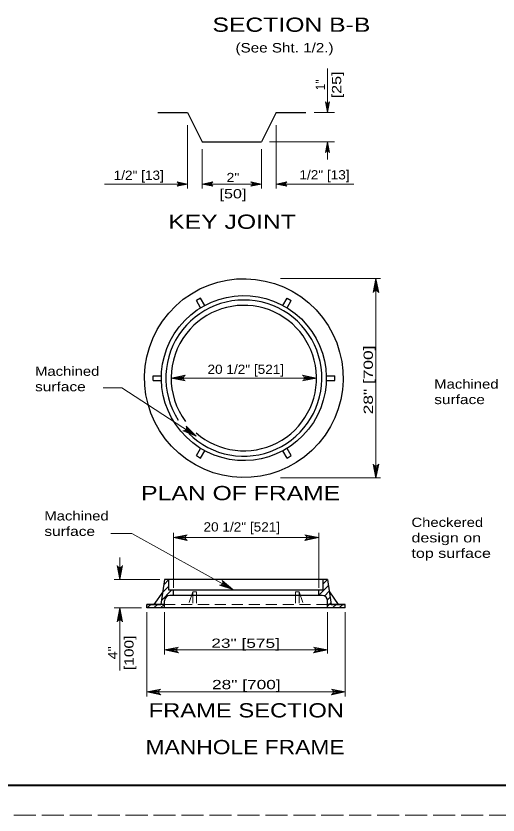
# Model space of a CAD drawing. Extents: x 758.3 to 792.3, y 849.7 to 893.7.
# Drawn here: x 775.35 to 783.49, y 849.69 to 863.16 of the extents above; entities that cross this region are included whole.
import ezdxf
from ezdxf.enums import TextEntityAlignment as Align

# ---------------------------------------------------------------- set-up
doc = ezdxf.new("R2010")
doc.units = 0
doc.header["$LTSCALE"] = 0.062
doc.linetypes.add('LONG_DASHED', pattern=[7.5, 6, -1.5])
doc.linetypes.add('MEDIUM_DASHED', pattern=[4.5, 3, -1.5])
doc.layers.add('1', color=7, linetype='Continuous', lineweight=13)

msp = doc.modelspace()

# ---------------------------------------------------------------- linework, layer by layer
at = {"layer": '1'}
for p, q in [((780.60933, 861.53942), (780.60933, 862.2805)), ((780.58692, 861.69967), (780.60933, 861.53942)), ((780.63408, 861.7015), (780.60933, 861.53942)), ((780.598, 861.69425), (780.60933, 861.53942)), ((780.62375, 861.69542), (780.60933, 861.53942)), ((780.60933, 861.69258), (780.60933, 861.53942)), ((780.38242, 861.53808), (780.72908, 861.53808)), ((778.24467, 861.32258), (778.24467, 860.253)), ((779.74392, 861.32258), (779.74392, 860.253)), ((779.63217, 861.03967), (780.72908, 861.03967)), ((780.58458, 860.87758), (780.60933, 861.03967)), ((780.59492, 860.88367), (780.60933, 861.03967)), ((780.60933, 860.74433), (780.60933, 861.03967)), ((780.60933, 860.8865), (780.60933, 861.03967)), ((780.62067, 860.88483), (780.60933, 861.03967)), ((780.63175, 860.87942), (780.60933, 861.03967)), ((778.4945, 860.91733), (778.4945, 860.253)), ((779.494, 860.91733), (779.494, 860.253)), ((778.08442, 860.35233), (778.24467, 860.32992)), ((778.65475, 860.35233), (778.4945, 860.32992)), ((779.33383, 860.35233), (779.494, 860.32992)), ((779.90417, 860.35233), (779.74392, 860.32992)), ((776.84475, 860.32992), (778.24467, 860.32992)), ((778.0825, 860.30508), (778.24467, 860.32992)), ((778.08867, 860.3155), (778.24467, 860.32992)), ((778.08983, 860.34125), (778.24467, 860.32992)), ((778.0915, 860.32992), (778.24467, 860.32992)), ((778.64933, 860.34125), (778.4945, 860.32992)), ((778.64767, 860.32992), (778.4945, 860.32992)), ((778.6505, 860.3155), (778.4945, 860.32992)), ((778.65667, 860.30508), (778.4945, 860.32992)), ((779.33192, 860.30508), (779.494, 860.32992)), ((779.33808, 860.3155), (779.494, 860.32992)), ((779.33925, 860.34125), (779.494, 860.32992)), ((779.34092, 860.32992), (779.494, 860.32992)), ((779.89875, 860.34125), (779.74392, 860.32992)), ((779.74392, 860.32992), (781.05142, 860.32992)), ((779.89708, 860.32992), (779.74392, 860.32992)), ((779.89992, 860.3155), (779.74392, 860.32992)), ((779.90608, 860.30508), (779.74392, 860.32992)), ((779.81358, 858.73542), (781.50583, 858.73542)), ((781.39425, 858.51958), (781.42717, 858.73542)), ((781.408, 858.52775), (781.42717, 858.73542)), ((781.42717, 858.53158), (781.42717, 858.73542)), ((781.44225, 858.52933), (781.42717, 858.73542)), ((781.457, 858.52217), (781.42717, 858.73542)), ((778.18233, 857.08708), (777.96908, 857.05725)), ((778.17517, 857.07233), (777.96908, 857.05725)), ((779.59, 857.05725), (777.96908, 857.05725)), ((778.17292, 857.05725), (777.96908, 857.05725)), ((778.17675, 857.03808), (777.96908, 857.05725)), ((778.18492, 857.02433), (777.96908, 857.05725)), ((779.59, 857.05725), (780.4235, 857.05725)), ((780.20767, 857.02433), (780.4235, 857.05725)), ((780.21017, 857.08708), (780.4235, 857.05725)), ((780.21583, 857.03808), (780.4235, 857.05725)), ((780.21742, 857.07233), (780.4235, 857.05725)), ((780.21958, 857.05725), (780.4235, 857.05725)), ((778.21125, 856.18008), (778.38992, 856.07633)), ((778.22158, 856.19133), (778.38992, 856.07633)), ((778.22925, 856.20925), (778.38992, 856.07633)), ((778.23033, 856.22525), (778.38992, 856.07633)), ((778.19692, 856.172), (778.38992, 856.07633)), ((781.39733, 855.58467), (781.42717, 855.37133)), ((781.41208, 855.57742), (781.42717, 855.37133)), ((781.46017, 855.58717), (781.42717, 855.37133)), ((781.44633, 855.579), (781.42717, 855.37133)), ((781.42717, 855.57525), (781.42717, 855.37133)), ((779.81358, 855.37775), (781.50583, 855.37775)), ((778.00583, 853.51958), (778.00583, 854.44617)), ((780.46033, 853.51958), (780.46033, 854.44617)), ((778.21908, 854.39733), (778.00583, 854.3675)), ((778.21183, 854.38258), (778.00583, 854.3675)), ((778.20967, 854.3675), (778.00583, 854.3675)), ((778.21342, 854.34833), (778.00583, 854.3675)), ((778.22158, 854.3345), (778.00583, 854.3675)), ((780.46033, 854.3675), (778.00583, 854.3675)), ((780.2445, 854.3345), (780.46033, 854.3675)), ((780.24708, 854.39733), (780.46033, 854.3675)), ((780.25275, 854.34833), (780.46033, 854.3675)), ((780.25425, 854.38258), (780.46033, 854.3675)), ((780.2565, 854.3675), (780.46033, 854.3675)), ((778.00583, 853.973), (778.00583, 854.26283)), ((780.46033, 853.973), (780.46033, 854.26283)), ((777.10258, 853.6595), (777.10258, 854.03017)), ((777.07275, 853.87267), (777.10258, 853.65942)), ((777.0875, 853.8655), (777.10258, 853.65942)), ((777.13558, 853.87525), (777.10258, 853.65942)), ((777.12175, 853.86708), (777.10258, 853.65942)), ((777.10258, 853.86325), (777.10258, 853.65942)), ((777.77742, 853.6595), (777.00767, 853.6595)), ((777.84367, 853.57225), (777.93092, 853.6595)), ((778.84008, 853.61992), (779.01233, 853.49067)), ((780.53517, 853.58458), (780.61, 853.6595)), ((777.80608, 853.30883), (777.97708, 853.47992)), ((777.82483, 853.44058), (777.93092, 853.54667)), ((778.8075, 853.56617), (779.01233, 853.49067)), ((778.82133, 853.57425), (779.01233, 853.49067)), ((778.83383, 853.58925), (779.01233, 853.49067)), ((778.83925, 853.6035), (779.01233, 853.49067)), ((780.46033, 853.397), (780.62417, 853.56075)), ((778.00083, 853.39067), (778.005, 853.39483)), ((780.55808, 853.38183), (780.63817, 853.46192)), ((780.60808, 853.319), (780.65233, 853.36325)), ((777.56483, 853.18058), (777.62475, 853.2405)), ((777.67775, 853.18058), (777.73758, 853.2405)), ((777.79075, 853.18058), (777.85067, 853.2405)), ((780.61, 853.20808), (780.66642, 853.2645)), ((780.69542, 853.18058), (780.75533, 853.2405)), ((780.80842, 853.18058), (780.86833, 853.2405)), ((777.46717, 853.18058), (777.00767, 853.18058)), ((777.06967, 852.96483), (777.10258, 853.18058)), ((777.08342, 852.973), (777.10258, 853.18058)), ((777.10258, 852.97675), (777.10258, 853.18058)), ((777.11767, 852.97458), (777.10258, 853.18058)), ((777.13242, 852.96733), (777.10258, 853.18058)), ((777.10258, 852.12292), (777.10258, 853.17883)), ((777.55683, 853.11142), (777.55683, 851.68592)), ((777.55683, 853.091), (777.55683, 852.4505)), ((777.85617, 853.11142), (777.85617, 852.39392)), ((777.85617, 853.091), (777.85617, 852.68567)), ((780.61, 853.11142), (780.61, 852.41217)), ((780.61, 853.091), (780.61, 852.68567)), ((780.90933, 853.11142), (780.90933, 851.68592)), ((780.90933, 853.091), (780.90933, 852.4505)), ((777.55992, 852.47258), (777.55683, 852.47258)), ((778.06942, 852.50242), (777.85617, 852.47258)), ((778.06217, 852.48767), (777.85617, 852.47258)), ((778.06, 852.47258), (777.85617, 852.47258)), ((778.06375, 852.45342), (777.85617, 852.47258)), ((778.07192, 852.43967), (777.85617, 852.47258)), ((780.61, 852.47258), (777.85617, 852.47258)), ((780.39417, 852.43967), (780.61, 852.47258)), ((780.39675, 852.50242), (780.61, 852.47258)), ((780.40242, 852.45342), (780.61, 852.47258)), ((780.40392, 852.48767), (780.61, 852.47258)), ((780.40617, 852.47258), (780.61, 852.47258)), ((777.77008, 851.79442), (777.55683, 851.76458)), ((777.76283, 851.77967), (777.55683, 851.76458)), ((777.76067, 851.76458), (777.55683, 851.76458)), ((777.76442, 851.74542), (777.55683, 851.76458)), ((777.77258, 851.73158), (777.55683, 851.76458)), ((780.90933, 851.76458), (777.55683, 851.76458)), ((780.69358, 851.73158), (780.90933, 851.76458)), ((780.69608, 851.79442), (780.90933, 851.76458)), ((780.70175, 851.74542), (780.90933, 851.76458)), ((780.70325, 851.77967), (780.90933, 851.76458)), ((780.7055, 851.76458), (780.90933, 851.76458))]:
    msp.add_line(p, q, dxfattribs=at)
at = {"layer": '1', "lineweight": 25}
for p, q in [((777.74483, 861.53942), (778.24467, 861.53942)), ((778.24467, 861.53942), (778.4945, 861.03967)), ((779.74392, 861.53942), (779.494, 861.03967)), ((779.74392, 861.53942), (780.24367, 861.53942)), ((778.4945, 861.03967), (779.494, 861.03967)), ((778.46408, 858.40533), (778.39483, 858.36533)), ((778.466, 858.24217), (778.39483, 858.36533)), ((778.53517, 858.28217), (778.46408, 858.40533)), ((779.85725, 858.28217), (779.92842, 858.40533)), ((779.9265, 858.24217), (779.99758, 858.36533)), ((779.92842, 858.40533), (779.99758, 858.36533)), ((777.66275, 857.09708), (777.805, 857.09708)), ((777.66275, 857.01742), (777.66275, 857.09708)), ((777.66275, 857.01742), (777.805, 857.01742)), ((780.58767, 857.09708), (780.73, 857.09708)), ((780.58767, 857.01742), (780.73, 857.01742)), ((780.73, 857.01742), (780.73, 857.09708)), ((778.39483, 855.74942), (778.466, 855.8725)), ((778.46425, 855.7095), (778.53533, 855.8325)), ((779.92867, 855.7095), (779.85742, 855.83258)), ((779.99775, 855.74933), (779.9265, 855.8725)), ((778.39483, 855.74942), (778.46425, 855.7095)), ((779.92867, 855.7095), (779.99775, 855.74933)), ((777.85617, 853.6595), (777.79625, 853.2405)), ((777.93092, 853.47992), (777.93092, 853.6595)), ((780.53517, 853.47992), (780.53517, 853.6595)), ((780.61, 853.6595), (780.66992, 853.2405)), ((780.53517, 853.47992), (777.93092, 853.47992)), ((778.00583, 853.39017), (778.00583, 853.47992)), ((780.46033, 853.39017), (780.46033, 853.47992)), ((777.82617, 853.45), (777.6765, 853.2405)), ((780.52025, 853.39017), (777.94592, 853.39017)), ((780.63992, 853.45), (780.78958, 853.2405)), ((777.55683, 853.2405), (777.79625, 853.2405)), ((777.85617, 853.2405), (777.55683, 853.2405)), ((777.85617, 853.18058), (777.85617, 853.30033)), ((780.61, 853.18058), (780.61, 853.30033)), ((780.90933, 853.2405), (780.61, 853.2405)), ((780.66992, 853.2405), (780.90933, 853.2405)), ((780.90933, 853.18058), (780.90933, 853.2405))]:
    msp.add_line(p, q, dxfattribs=at)
at = {"layer": '1', "linetype": 'MEDIUM_DASHED'}
for p, q in [((778.33508, 853.45), (778.26325, 853.2405)), ((778.33508, 853.45), (778.33508, 853.2405)), ((778.33508, 853.45), (778.39492, 853.45)), ((778.39492, 853.45), (778.39492, 853.2405)), ((780.07117, 853.45), (780.07117, 853.2405)), ((780.07117, 853.45), (780.13108, 853.45)), ((780.13108, 853.45), (780.13108, 853.2405)), ((780.13108, 853.45), (780.20292, 853.2405)), ((780.61, 853.2405), (777.85617, 853.2405))]:
    msp.add_line(p, q, dxfattribs=at)
at = {"layer": '1', "linetype": 'LONG_DASHED'}
msp.add_lwpolyline([(758.3205, 849.68817), (792.3205, 849.68817), (792.3205, 871.68817), (758.3205, 871.68817)], close=True, dxfattribs=at)
at = {"layer": '1', "lineweight": 25}
for points in [[(791.8205, 850.18817), (760.3205, 850.18817), (760.3205, 871.18817)], [(780.61, 853.6595), (779.00958, 853.6595), (777.85617, 853.6595)], [(780.90933, 853.18058), (777.55683, 853.18058), (777.55683, 853.2405)]]:
    msp.add_lwpolyline(points, dxfattribs=at)
at = {"layer": '1', "lineweight": 40}
msp.add_lwpolyline([(760.3205, 871.18817), (791.8205, 871.18817), (791.8205, 850.18817), (760.3205, 850.18817)], close=True, dxfattribs=at)
at = {"layer": '1'}
for points in [[(780.64475, 861.71642), (780.60933, 861.53942), (780.57392, 861.71642)], [(780.57392, 860.86267), (780.60933, 861.03967), (780.64475, 860.86267)], [(778.06767, 860.2945), (778.24467, 860.32992), (778.06767, 860.36525)], [(778.6715, 860.2945), (778.4945, 860.32992), (778.6715, 860.36525)], [(779.317, 860.2945), (779.494, 860.32992), (779.317, 860.36525)], [(779.92092, 860.2945), (779.74392, 860.32992), (779.92092, 860.36525)], [(778.4945, 860.32992), (779.15267, 860.32992), (779.494, 860.32992)], [(781.38008, 858.49983), (781.42717, 858.73542), (781.47433, 858.49983)], [(781.42717, 858.73542), (781.42717, 856.7055), (781.42717, 855.37133)], [(778.20467, 857.01017), (777.96908, 857.05725), (778.20467, 857.10442)], [(780.18792, 857.01017), (780.4235, 857.05725), (780.18792, 857.10442)], [(778.38992, 856.07633), (777.1385, 856.89525), (776.82342, 856.89525)], [(778.22192, 856.24808), (778.38992, 856.07633), (778.16875, 856.17033)], [(781.47433, 855.60692), (781.42717, 855.37133), (781.38008, 855.60692)], [(779.01233, 853.49067), (777.30233, 854.43658), (776.94942, 854.43658)], [(778.24142, 854.32042), (778.00583, 854.3675), (778.24142, 854.41458)], [(780.22475, 854.32042), (780.46033, 854.3675), (780.22475, 854.41458)], [(777.14975, 853.895), (777.10258, 853.65942), (777.0555, 853.895)], [(778.78333, 853.56333), (779.01233, 853.49067), (778.82892, 853.64583)], [(777.0555, 852.945), (777.10258, 853.18058), (777.14975, 852.945)], [(778.09175, 852.4255), (777.85617, 852.47258), (778.09175, 852.51975)], [(780.37442, 852.4255), (780.61, 852.47258), (780.37442, 852.51975)], [(777.79242, 851.7175), (777.55683, 851.76458), (777.79242, 851.81175)], [(780.67375, 851.7175), (780.90933, 851.76458), (780.67375, 851.81175)]]:
    msp.add_lwpolyline(points, dxfattribs=at)
for centre, radius, start, end in [((780.6093, 861.7307), 0.0382, 202.08782, 337.91395), ((780.60938, 860.8484), 0.0382, 22.08782, 157.91395), ((778.05333, 860.32993), 0.0382, 292.08605, 67.91218), ((778.68581, 860.32993), 0.0382, 112.08782, 247.91395), ((779.30275, 860.32993), 0.0382, 292.08605, 67.91218), ((779.93522, 860.32993), 0.0382, 112.08782, 247.91395), ((781.42724, 858.4808), 0.05085, 22.08782, 157.91395), ((778.22369, 857.05733), 0.05085, 112.08782, 247.91395), ((780.16885, 857.05733), 0.05085, 292.08605, 67.91218), ((778.17962, 856.2199), 0.05085, 257.75706, 33.58319), ((781.42714, 855.62598), 0.05085, 202.08782, 337.91395), ((778.26042, 854.36755), 0.05085, 112.08782, 247.91395), ((780.20573, 854.36755), 0.05085, 292.08605, 67.91218), ((777.10256, 853.91403), 0.05085, 202.08782, 337.91395), ((778.78947, 853.61381), 0.05085, 263.17667, 39.0028), ((777.10267, 852.92599), 0.05085, 22.08782, 157.91395), ((778.11075, 852.47266), 0.05085, 112.08782, 247.91395), ((780.35539, 852.47266), 0.05085, 292.08605, 67.91218), ((777.81141, 851.76466), 0.05085, 112.08782, 247.91395), ((780.65473, 851.76466), 0.05085, 292.08605, 67.91218)]:
    msp.add_arc(centre, radius, start, end, dxfattribs=at)
at = {"layer": '1', "lineweight": 25}
for centre, major_axis, start_param, end_param in [((779.19627, 857.05728), (1.67627, 0), 2.42912855, 8.71231376), ((779.19627, 857.05728), (1.3919, 0), 2.4720286, 8.75521386), ((779.19627, 857.05728), (1.31707, 0), 3.92866667, 8.76006136), ((779.19627, 857.05728), (1.22727, 0), 3.99445434, 8.76397434), ((779.19627, 857.05728), (1.31707, 0), 2.47687615, 3.7109351), ((779.19627, 857.05728), (1.22727, 0), 2.48078904, 3.78077145), ((777.94594, 853.30033), (-0.0898, 0), 4.71238893, 6.28318521), ((780.52021, 853.30033), (0.0898, 0), 6.28318526, 7.85398154)]:
    msp.add_ellipse(centre, major_axis=major_axis, ratio=0.999895, start_param=start_param, end_param=end_param, dxfattribs=at)

# ---------------------------------------------------------------- texts
at = {"layer": '1'}
for s, height, width, p in [('SECTION B-B', 0.24, 1.3, (778.6665, 862.89792)), ('(See Sht. 1/2.)', 0.16, 1.2, (779.05558, 862.54908)), ('KEY JOINT', 0.24, 1.3, (777.91925, 859.575)), ('Machined', 0.156, 1.2, (775.671, 857.09567)), ('surface', 0.156, 1.25, (775.671, 856.835)), ('Machined', 0.156, 1.2, (782.41142, 856.87925)), ('surface', 0.156, 1.25, (782.41142, 856.61858)), ('PLAN OF FRAME', 0.24, 1.3, (777.462, 854.99842)), ('Machined', 0.156, 1.2, (775.82833, 854.656)), ('Checkered', 0.156, 1.2, (782.02658, 854.547)), ('surface', 0.156, 1.25, (775.82833, 854.39533)), ('20 1/2" [521]', 0.156, 1.1, (778.51525, 854.46992)), ('design on', 0.156, 1.3, (782.02658, 854.28633)), ('top surface', 0.156, 1.3, (782.02658, 854.02567)), ('23" [575]', 0.156, 1.4, (778.64675, 852.508)), ('28" [700]', 0.156, 1.4, (778.65883, 851.81075)), ('FRAME SECTION', 0.24, 1.25, (777.58842, 851.33408)), ('MANHOLE FRAME', 0.24, 1.2, (777.53733, 850.71425))]:
    msp.add_text(s, height=height, dxfattribs=dict(at, width=width)).set_placement(p)
for s, width, p in [('[25]', 1.3, (780.83975, 862.00317)), ('1"', 0.95, (780.56575, 862.00325)), ('[100]', 1.25, (777.33417, 852.42387)), ('4"', 1.15, (777.06017, 852.42396))]:
    msp.add_text(s, height=0.156, rotation=90, dxfattribs=dict(at, width=width)).set_placement(p, align=Align.CENTER)
for s, width, p in [('1/2" [13]', 1.1, (777.42183, 860.40108)), ('2"', 1.15, (779.01242, 860.36242)), ('1/2" [13]', 1.1, (780.55858, 860.408)), ('[50]', 1.3, (779.0125, 860.08842)), ('20 1/2" [521]', 1.1, (779.22967, 857.12833))]:
    msp.add_text(s, height=0.156, dxfattribs=dict(at, width=width)).set_placement(p, align=Align.CENTER)
at = {"layer": '1', "width": 1.4}
msp.add_text('28" [700]', height=0.156, rotation=90, dxfattribs=at).set_placement((781.3745, 856.447))

doc.saveas('drawing.dxf')
